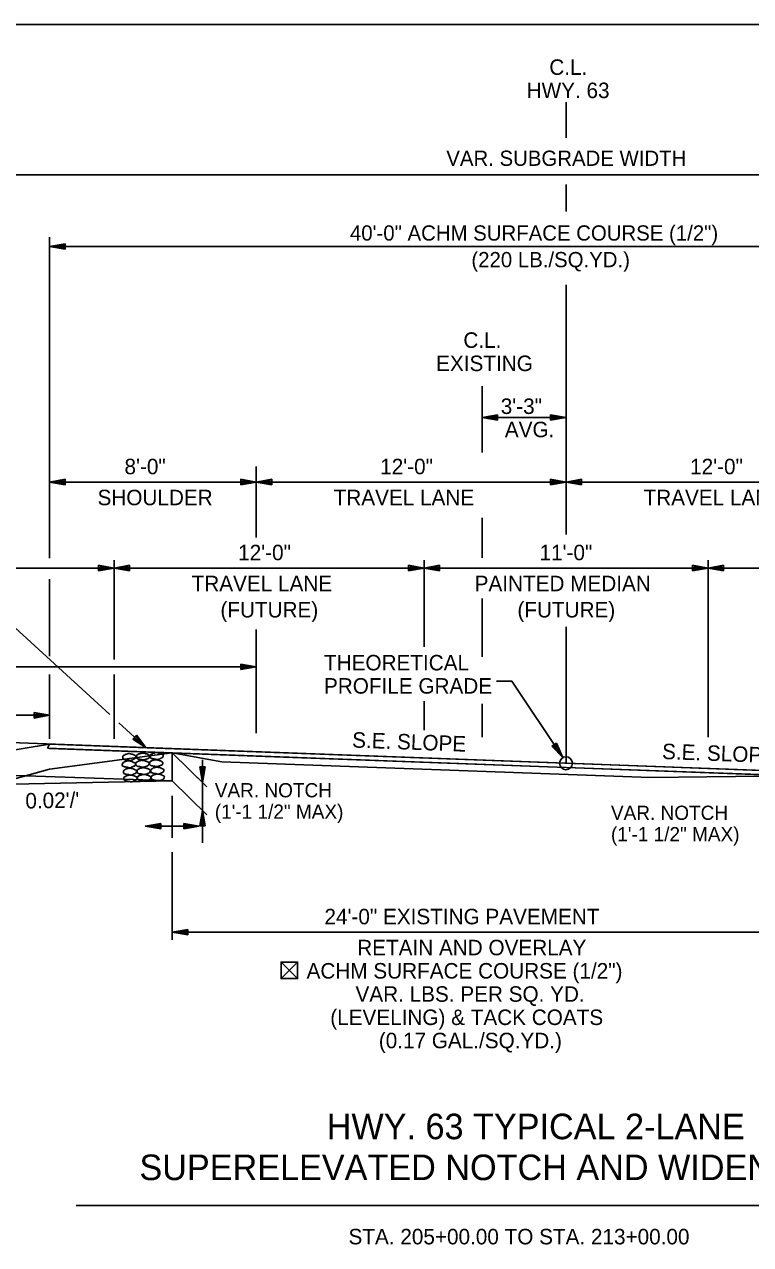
# Model space of a CAD drawing. Extents: x 1461846 to 1462006, y 1686171 to 1686805.
# Drawn here: x 1461905.15 to 1461933.27, y 1686625.69 to 1686672.94 of the extents above; entities that cross this region are included whole.
import ezdxf

# ---------------------------------------------------------------- set-up
doc = ezdxf.new("R2010")
doc.units = 0
for name, color, linetype in [('1', 7, 'Continuous'), ('10', 7, 'Continuous'), ('12', 7, 'Continuous'), ('19', 7, 'Continuous'), ('20', 7, 'Continuous'), ('3', 7, 'Continuous'), ('42', 7, 'Continuous'), ('R_Draft', 7, 'Continuous')]:
    doc.layers.add(name, color=color, linetype=linetype)

# ---------------------------------------------------------------- blocks, each defined once
blk = doc.blocks.new('ROCKS')
at = {"layer": '1'}
blk.add_spline([(0.013, 0.06), (0.053, 0.053), (0.107, 0.033), (0.133, 0.013), (0.133, -0.007), (0.12, -0.033), (0.107, -0.04), (0.073, -0.053), (0.033, -0.067), (0.013, -0.067), (-0.02, -0.06), (-0.06, -0.053), (-0.087, -0.047), (-0.113, -0.02), (-0.113, -0.007), (-0.107, 0.02), (-0.087, 0.033), (-0.067, 0.047), (-0.033, 0.053), (-0.02, 0.06), (0.013, 0.06)], degree=3, dxfattribs=at)

msp = doc.modelspace()

# ---------------------------------------------------------------- linework, layer by layer
at = {"layer": '10'}
for p, q in [((1461964.759, 1686672.939), (1461846.353, 1686672.939)), ((1461915.724, 1686636.633), (1461915.082, 1686635.991)), ((1461915.082, 1686636.633), (1461915.724, 1686635.991))]:
    msp.add_line(p, q, dxfattribs=at)
msp.add_lwpolyline([(1461915.475, 1686635.991), (1461915.724, 1686635.991), (1461915.724, 1686636.633), (1461915.082, 1686636.633), (1461915.082, 1686635.991), (1461915.464, 1686635.991)], dxfattribs=at)
at = {"layer": '19'}
for p, q in [((1461926.121, 1686668.543), (1461926.121, 1686669.934)), ((1461926.121, 1686665.696), (1461926.121, 1686666.742)), ((1461926.121, 1686653.183), (1461926.121, 1686662.852)), ((1461922.871, 1686656.358), (1461922.871, 1686658.937)), ((1461922.871, 1686652.278), (1461922.871, 1686653.838)), ((1461922.871, 1686648.445), (1461922.871, 1686650.706)), ((1461904.634, 1686649.718), (1461908.455, 1686646.215)), ((1461926.121, 1686644.332), (1461926.121, 1686649.608)), ((1461884.121, 1686648.063), (1461914.121, 1686648.063)), ((1461913.521, 1686648.168), (1461913.521, 1686647.958)), ((1461914.121, 1686648.063), (1461913.521, 1686648.168)), ((1461913.961, 1686648.078), (1461913.521, 1686648.113)), ((1461913.521, 1686647.958), (1461914.121, 1686648.063)), ((1461913.521, 1686648.008), (1461913.961, 1686648.048)), ((1461922.871, 1686645.345), (1461922.871, 1686646.634)), ((1461908.799, 1686645.899), (1461909.852, 1686644.934)), ((1461909.338, 1686645.262), (1461909.48, 1686645.417)), ((1461909.852, 1686644.934), (1461909.338, 1686645.262)), ((1461909.724, 1686645.031), (1461909.372, 1686645.299)), ((1461909.443, 1686645.377), (1461909.744, 1686645.053)), ((1461909.48, 1686645.417), (1461909.852, 1686644.934)), ((1461925.744, 1686645.103), (1461925.571, 1686644.987)), ((1461925.99, 1686644.546), (1461925.744, 1686645.103)), ((1461906.121, 1686645.072), (1461884.121, 1686641.406)), ((1461906.039, 1686644.909), (1461910.121, 1686644.758)), ((1461906.121, 1686645.072), (1461914.121, 1686644.776)), ((1461906.121, 1686644.906), (1461914.121, 1686644.61)), ((1461910.871, 1686643.648), (1461910.871, 1686644.73)), ((1461926.121, 1686644.332), (1461914.121, 1686644.776)), ((1461925.571, 1686644.987), (1461925.99, 1686644.546)), ((1461925.611, 1686645.009), (1461925.888, 1686644.671)), ((1461925.91, 1686644.683), (1461925.702, 1686645.069)), ((1461911.933, 1686644.187), (1461912.143, 1686644.187)), ((1461912.038, 1686643.587), (1461911.933, 1686644.187)), ((1461912.023, 1686643.747), (1461911.983, 1686644.187)), ((1461912.143, 1686644.187), (1461912.038, 1686643.587)), ((1461912.088, 1686644.187), (1461912.053, 1686643.747)), ((1461926.121, 1686644.166), (1461914.121, 1686644.61)), ((1461938.121, 1686643.888), (1461926.121, 1686644.332)), ((1461938.121, 1686643.722), (1461926.121, 1686644.166)), ((1461896.568, 1686644.134), (1461910.871, 1686643.648)), ((1461910.871, 1686643.648), (1461895.93, 1686643.349)), ((1461911.933, 1686641.905), (1461912.038, 1686642.505)), ((1461911.988, 1686641.905), (1461912.023, 1686642.345)), ((1461912.038, 1686642.505), (1461912.143, 1686641.905)), ((1461912.053, 1686642.345), (1461912.093, 1686641.905)), ((1461912.143, 1686641.905), (1461911.933, 1686641.905))]:
    msp.add_line(p, q, dxfattribs=at)
for points in [[(1461923.421, 1686647.504), (1461924.021, 1686647.504), (1461925.99, 1686644.546)], [(1461955.621, 1686643.241), (1461896.621, 1686645.424)]]:
    msp.add_lwpolyline(points, dxfattribs=at)
msp.add_lwpolyline([(1461906.039, 1686644.909), (1461909.845, 1686644.768), (1461946.206, 1686643.422), (1461946.206, 1686643.422), (1461946.206, 1686643.422), (1461946.121, 1686643.592), (1461946.121, 1686643.592), (1461946.121, 1686643.592), (1461909.898, 1686644.932), (1461906.121, 1686645.072)], close=True, dxfattribs=at)
msp.add_circle((1461926.116, 1686644.33), 0.25, dxfattribs=at)
at = {"layer": '20'}
for p, q in [((1461895.93, 1686667.113), (1461956.082, 1686667.113)), ((1461906.121, 1686655.82), (1461906.121, 1686664.695)), ((1461906.721, 1686664.448), (1461906.121, 1686664.343)), ((1461906.121, 1686664.343), (1461946.206, 1686664.343)), ((1461906.121, 1686664.343), (1461906.721, 1686664.238)), ((1461906.721, 1686664.393), (1461906.281, 1686664.358)), ((1461906.281, 1686664.328), (1461906.721, 1686664.288)), ((1461906.721, 1686664.238), (1461906.721, 1686664.448)), ((1461922.871, 1686657.721), (1461923.471, 1686657.826)), ((1461926.121, 1686657.721), (1461922.871, 1686657.721)), ((1461923.471, 1686657.616), (1461922.871, 1686657.721)), ((1461923.031, 1686657.736), (1461923.471, 1686657.771)), ((1461923.471, 1686657.666), (1461923.031, 1686657.706)), ((1461923.471, 1686657.826), (1461923.471, 1686657.616)), ((1461925.521, 1686657.826), (1461925.521, 1686657.616)), ((1461926.121, 1686657.721), (1461925.521, 1686657.826)), ((1461925.961, 1686657.736), (1461925.521, 1686657.771)), ((1461925.521, 1686657.616), (1461926.121, 1686657.721)), ((1461925.521, 1686657.666), (1461925.961, 1686657.706)), ((1461906.121, 1686652.274), (1461906.121, 1686655.82)), ((1461914.121, 1686653.072), (1461914.121, 1686655.82)), ((1461906.721, 1686655.325), (1461906.121, 1686655.22)), ((1461906.121, 1686655.22), (1461914.121, 1686655.22)), ((1461906.121, 1686655.22), (1461906.721, 1686655.115)), ((1461906.721, 1686655.27), (1461906.281, 1686655.235)), ((1461906.281, 1686655.205), (1461906.721, 1686655.165)), ((1461906.721, 1686655.115), (1461906.721, 1686655.325)), ((1461913.521, 1686655.325), (1461913.521, 1686655.115)), ((1461914.121, 1686655.22), (1461913.521, 1686655.325)), ((1461913.961, 1686655.235), (1461913.521, 1686655.27)), ((1461913.521, 1686655.115), (1461914.121, 1686655.22)), ((1461913.521, 1686655.165), (1461913.961, 1686655.205)), ((1461914.721, 1686655.325), (1461914.121, 1686655.22)), ((1461914.121, 1686655.22), (1461926.121, 1686655.22)), ((1461914.121, 1686655.22), (1461914.721, 1686655.115)), ((1461914.721, 1686655.27), (1461914.281, 1686655.235)), ((1461914.281, 1686655.205), (1461914.721, 1686655.165)), ((1461914.721, 1686655.115), (1461914.721, 1686655.325)), ((1461925.521, 1686655.325), (1461925.521, 1686655.115)), ((1461926.121, 1686655.22), (1461925.521, 1686655.325)), ((1461925.961, 1686655.235), (1461925.521, 1686655.27)), ((1461925.521, 1686655.115), (1461926.121, 1686655.22)), ((1461925.521, 1686655.165), (1461925.961, 1686655.205)), ((1461926.121, 1686655.22), (1461926.721, 1686655.325)), ((1461938.121, 1686655.22), (1461926.121, 1686655.22)), ((1461926.721, 1686655.115), (1461926.121, 1686655.22)), ((1461926.281, 1686655.235), (1461926.721, 1686655.27)), ((1461926.721, 1686655.165), (1461926.281, 1686655.205)), ((1461926.721, 1686655.325), (1461926.721, 1686655.115)), ((1461908.621, 1686648.346), (1461908.621, 1686652.19)), ((1461920.621, 1686648.831), (1461920.621, 1686652.19)), ((1461931.621, 1686645.341), (1461931.621, 1686652.19)), ((1461896.621, 1686651.89), (1461908.621, 1686651.89)), ((1461908.021, 1686651.995), (1461908.021, 1686651.785)), ((1461908.621, 1686651.89), (1461908.021, 1686651.995)), ((1461908.461, 1686651.905), (1461908.021, 1686651.94)), ((1461908.021, 1686651.785), (1461908.621, 1686651.89)), ((1461908.021, 1686651.835), (1461908.461, 1686651.875)), ((1461908.621, 1686651.89), (1461909.221, 1686651.995)), ((1461908.621, 1686651.89), (1461920.621, 1686651.89)), ((1461909.221, 1686651.785), (1461908.621, 1686651.89)), ((1461908.781, 1686651.905), (1461909.221, 1686651.94)), ((1461909.221, 1686651.835), (1461908.781, 1686651.875)), ((1461909.221, 1686651.995), (1461909.221, 1686651.785)), ((1461920.021, 1686651.995), (1461920.021, 1686651.785)), ((1461920.621, 1686651.89), (1461920.021, 1686651.995)), ((1461920.461, 1686651.905), (1461920.021, 1686651.94)), ((1461920.021, 1686651.785), (1461920.621, 1686651.89)), ((1461920.021, 1686651.835), (1461920.461, 1686651.875)), ((1461920.621, 1686651.89), (1461921.221, 1686651.995)), ((1461920.621, 1686651.89), (1461931.621, 1686651.89)), ((1461921.221, 1686651.785), (1461920.621, 1686651.89)), ((1461920.781, 1686651.905), (1461921.221, 1686651.94)), ((1461921.221, 1686651.835), (1461920.781, 1686651.875)), ((1461921.221, 1686651.995), (1461921.221, 1686651.785)), ((1461931.021, 1686651.995), (1461931.021, 1686651.785)), ((1461931.621, 1686651.89), (1461931.021, 1686651.995)), ((1461931.461, 1686651.905), (1461931.021, 1686651.94)), ((1461931.021, 1686651.785), (1461931.621, 1686651.89)), ((1461931.021, 1686651.835), (1461931.461, 1686651.875)), ((1461931.621, 1686651.89), (1461932.221, 1686651.995)), ((1461943.621, 1686651.89), (1461931.621, 1686651.89)), ((1461932.221, 1686651.785), (1461931.621, 1686651.89)), ((1461931.781, 1686651.905), (1461932.221, 1686651.94)), ((1461932.221, 1686651.835), (1461931.781, 1686651.875)), ((1461932.221, 1686651.995), (1461932.221, 1686651.785)), ((1461906.121, 1686648.47), (1461906.121, 1686651.458)), ((1461914.121, 1686645.499), (1461914.121, 1686649.507)), ((1461906.121, 1686645.28), (1461906.121, 1686647.763)), ((1461908.621, 1686646.119), (1461908.621, 1686647.763)), ((1461920.621, 1686645.607), (1461920.621, 1686646.731)), ((1461895.93, 1686646.185), (1461906.121, 1686646.185)), ((1461905.521, 1686646.29), (1461905.521, 1686646.08)), ((1461906.121, 1686646.185), (1461905.521, 1686646.29)), ((1461905.961, 1686646.2), (1461905.521, 1686646.235)), ((1461905.521, 1686646.08), (1461906.121, 1686646.185)), ((1461905.521, 1686646.13), (1461905.961, 1686646.17)), ((1461908.621, 1686645.945), (1461908.621, 1686646.119)), ((1461908.621, 1686645.28), (1461908.621, 1686645.945)), ((1461910.871, 1686644.73), (1461912.154, 1686643.474)), ((1461910.871, 1686644.73), (1461912.215, 1686643.414)), ((1461910.871, 1686643.648), (1461912.215, 1686642.332))]:
    msp.add_line(p, q, dxfattribs=at)
msp.add_lwpolyline([(1461912.038, 1686644.464), (1461912.038, 1686641.254)], dxfattribs=at)
at = {"layer": '3'}
msp.add_line((1461907.149, 1686627.199), (1461945.094, 1686627.199), dxfattribs=at)
at = {"layer": '42'}
for p, q in [((1461910.871, 1686643.07), (1461910.871, 1686641.437)), ((1461910.423, 1686641.994), (1461909.823, 1686641.889)), ((1461909.823, 1686641.889), (1461910.423, 1686641.784)), ((1461911.918, 1686641.889), (1461909.823, 1686641.889)), ((1461910.423, 1686641.939), (1461909.983, 1686641.904)), ((1461909.983, 1686641.874), (1461910.423, 1686641.834)), ((1461910.423, 1686641.784), (1461910.423, 1686641.994)), ((1461911.318, 1686641.784), (1461911.318, 1686641.994)), ((1461911.318, 1686641.994), (1461911.918, 1686641.889)), ((1461911.318, 1686641.939), (1461911.758, 1686641.904)), ((1461911.918, 1686641.889), (1461911.318, 1686641.784)), ((1461911.758, 1686641.874), (1461911.318, 1686641.834))]:
    msp.add_line(p, q, dxfattribs=at)
at = {"layer": 'R_Draft'}
for p, q in [((1461910.871, 1686637.493), (1461910.871, 1686640.892)), ((1461910.871, 1686637.793), (1461911.471, 1686637.898)), ((1461934.871, 1686637.793), (1461910.871, 1686637.793)), ((1461911.471, 1686637.688), (1461910.871, 1686637.793)), ((1461911.031, 1686637.808), (1461911.471, 1686637.843)), ((1461911.471, 1686637.738), (1461911.031, 1686637.778)), ((1461911.471, 1686637.898), (1461911.471, 1686637.688))]:
    msp.add_line(p, q, dxfattribs=at)
msp.add_lwpolyline([(1462000.252, 1686643.294), (1461985.479, 1686642.773), (1461972.442, 1686642.427), (1461966.445, 1686641.94), (1461956.315, 1686639.45), (1461938.121, 1686642.877), (1461934.871, 1686643.842), (1461929.37, 1686643.781), (1461912.792, 1686644.39), (1461910.871, 1686644.73), (1461906.121, 1686644.095), (1461890.249, 1686639.689)], dxfattribs=at)

# ---------------------------------------------------------------- block references
at = {"layer": '19', "xscale": 2.061136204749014, "yscale": 2.061136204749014}
for p in [(1461909.188, 1686644.577), (1461909.716, 1686644.597), (1461910.246, 1686644.616), (1461909.169, 1686644.296), (1461909.697, 1686644.315), (1461909.744, 1686644.031), (1461910.227, 1686644.337), (1461910.273, 1686644.05), (1461909.215, 1686644.012), (1461909.232, 1686643.75), (1461909.761, 1686643.77), (1461910.29, 1686643.789)]:
    msp.add_blockref('ROCKS', p, dxfattribs=at)

# ---------------------------------------------------------------- texts
at = {"layer": '10'}
for s, height, p in [('12\'-0"', 0.6, (1461913.423, 1686652.19)), ('11\'-0"', 0.6, (1461925.093, 1686652.19)), ('TRAVEL LANE', 0.6, (1461911.621, 1686650.99)), ('PAINTED MEDIAN', 0.6, (1461922.58, 1686650.99)), ('(FUTURE)', 0.6, (1461912.736, 1686649.974)), ('(FUTURE)', 0.6, (1461924.236, 1686649.974)), ('VAR. NOTCH', 0.55, (1461912.519, 1686643.01)), ('(1\'-1 1/2" MAX)', 0.55, (1461912.519, 1686642.181)), ('VAR. NOTCH', 0.55, (1461927.858, 1686642.137)), ('(1\'-1 1/2" MAX)', 0.55, (1461927.858, 1686641.308))]:
    msp.add_text(s, height=height, dxfattribs=at).set_placement(p)
msp.add_text('STA. 205+00.00 TO STA. 213+00.00', height=0.6, rotation=359.9954, dxfattribs=at).set_placement((1461917.696, 1686625.7))
at = {"layer": '12'}
for s, p in [('HWY. 63 TYPICAL 2-LANE ', (1461916.853, 1686629.771)), ('SUPERELEVATED NOTCH AND WIDEN SECTION', (1461909.6, 1686628.188))]:
    msp.add_text(s, height=0.98999, rotation=359.9954, dxfattribs=at).set_placement(p)
at = {"layer": '42'}
for s, p in [('VAR. SUBGRADE WIDTH', (1461921.483, 1686667.462)), ('40\'-0" ACHM SURFACE COURSE (1/2")', (1461917.752, 1686664.568)), ('(220 LB./SQ.YD.)', (1461922.454, 1686663.536))]:
    msp.add_text(s, height=0.59001, rotation=360, dxfattribs=at).set_placement(p)
at = {"layer": 'R_Draft'}
for s, rotation, p in [('C.L.', 360, (1461925.472, 1686670.985)), ('HWY. 63', 360, (1461924.594, 1686670.085)), ('3\'-3"', 360, (1461923.59, 1686657.854)), ('AVG.', 360, (1461923.749, 1686656.954)), ('S.E. SLOPE', 357.881, (1461917.828, 1686644.939)), ('S.E. SLOPE', 357.881, (1461929.828, 1686644.495)), ("0.02'/'", 1.1458, (1461905.189, 1686642.573))]:
    msp.add_text(s, height=0.6, rotation=rotation, dxfattribs=at).set_placement(p)
for s, p in [('C.L.', (1461922.144, 1686660.415)), ('EXISTING', (1461921.088, 1686659.515)), ('8\'-0"', (1461909.022, 1686655.52)), ('12\'-0"', (1461918.923, 1686655.52)), ('12\'-0"', (1461930.923, 1686655.52)), ('SHOULDER', (1461907.978, 1686654.32)), ('TRAVEL LANE', (1461917.121, 1686654.32)), ('TRAVEL LANE', (1461929.121, 1686654.32)), ('THEORETICAL', (1461916.746, 1686647.925)), ('PROFILE GRADE', (1461916.746, 1686647.025)), ('24\'-0" EXISTING PAVEMENT', (1461916.764, 1686638.093)), ('RETAIN AND OVERLAY', (1461918.033, 1686636.893)), ('ACHM SURFACE COURSE (1/2")', (1461916.072, 1686635.993)), ('VAR. LBS. PER SQ. YD.', (1461917.967, 1686635.093)), ('(LEVELING) & TACK COATS', (1461916.989, 1686634.193)), ('(0.17 GAL./SQ.YD.)', (1461918.869, 1686633.293))]:
    msp.add_text(s, height=0.6, dxfattribs=at).set_placement(p)

doc.saveas('drawing.dxf')
